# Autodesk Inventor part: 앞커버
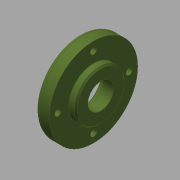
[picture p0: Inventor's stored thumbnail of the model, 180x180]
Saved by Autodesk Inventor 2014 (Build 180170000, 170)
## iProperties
Created: 2015-12
Part Number: 앞커버
Document SubType Name: Modeling
Designer: mdu
Density: 2.71 g/cm^3
Material: 알루미늄 6061
Appearance: 알루미늄 - 평지
Author: mdu
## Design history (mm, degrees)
sketch "스케치1"
  geometry: L1 (-7.5, 0)-(7.5, 0); L2 (-7.5, 0)-(-7.5, 31); L3 (-7.5, 31)-(2.5, 31); L4 (2.5, 31)-(2.5, 17.5); L5 (2.5, 17.5)-(7.5, 17.5); L6 (7.5, 17.5)-(7.5, 0); 2 further points
  constraints: 12 end point, 3 perpendicular, 1 coincident, 1 horizontal, 1 midpoint, 1 parallel
  dimensions: "d0" = 15 distance of L1.start L1.end; "d1" = 62 diameter of L3 L1; "d2" = 35 diameter of L5 L1; "d5" = 10 distance of L2.end L3.end
revolve "회전1" sketch "스케치1" stored, may be unused: angle "d6" = 90 deg
sketch "스케치2" dims "d42" = 50
  geometry: 3 further points
  constraints: 2 vertical alignment, 1 coincident, 2 other
hole "구멍1" sketch "스케치2" at (0, 25) diameter "d8" = 4.5; stored, may be unused: countersink angle "d12" = 90 deg, drill point angle "d14" = 118 deg; dims "d9" = 6, "d10" = 8, "d11" = 4.4, "d13" = 8
hole "구멍2" diameter "d20" = 18; stored, may be unused: countersink angle "d24" = 90 deg, drill point angle "d26" = 0 deg; dims "d18" = 10, "d19" = 10, "d21" = 6, "d22" = 8, "d23" = 4.4, "d25" = 8
hole "구멍3" diameter "d34" = 30; stored, may be unused: countersink angle "d38" = 90 deg, drill point angle "d40" = 0 deg; dims "d32" = 10, "d33" = 10, "d35" = 6, "d36" = 4, "d37" = 2, "d39" = 7.3
fillet "모깎기1" dims "d27" = 3, "d41" = 0.3
chamfer "모따기1" distance "d29" = 1; stored, may be unused: second distance "d30" = 2, angle "d31" = 45 deg
node "솔리드1"
pattern_circular "원형 패턴1" dims angle "d16" = 360 deg
